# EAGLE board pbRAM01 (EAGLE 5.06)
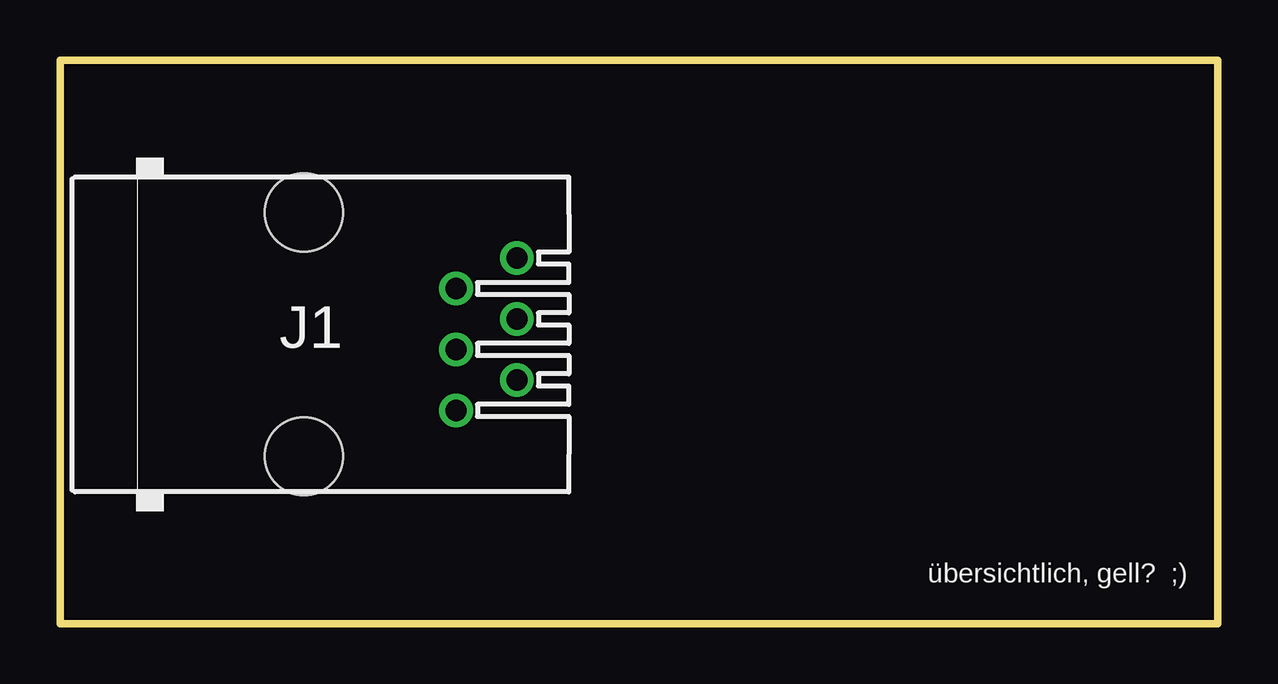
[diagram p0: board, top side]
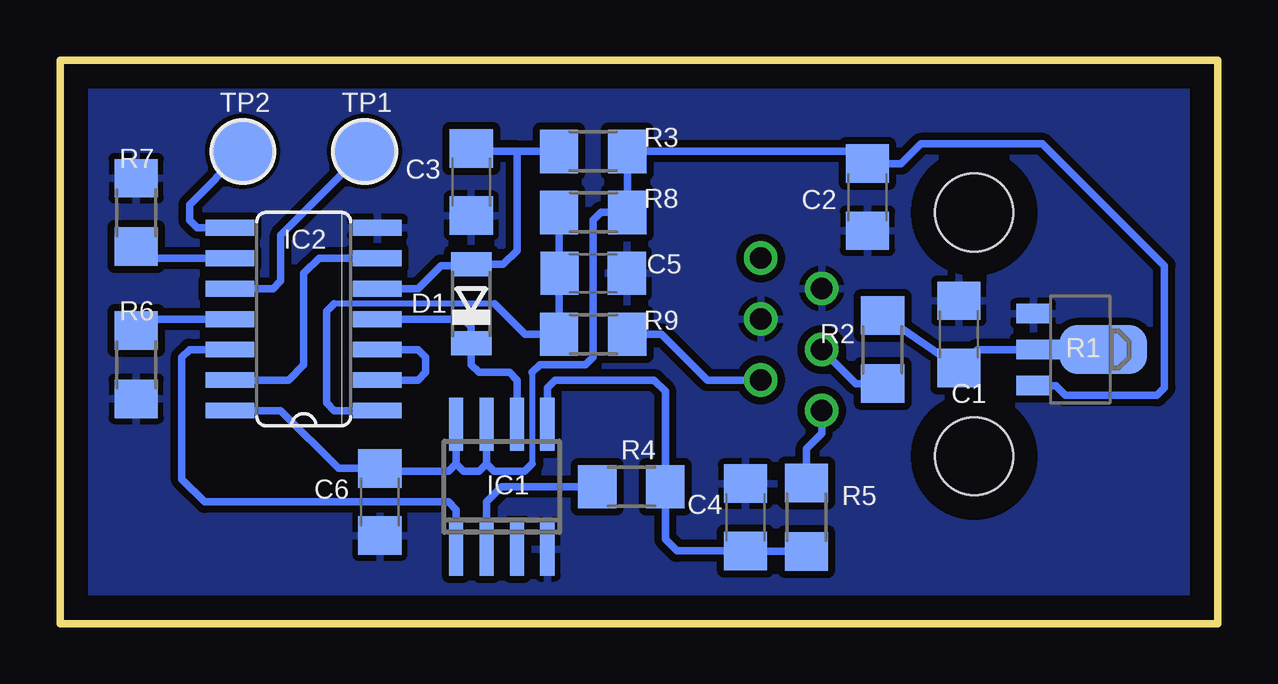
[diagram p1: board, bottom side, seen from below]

Size 48.26 x 23.5 mm. Coordinates in mm from the lower left corner, seen from the top.
Outline: 0,0 48.26,0 48.26,23.5 0,23.5 0,0
Copper layers (1*16): Top 0.035mm / dielectric 1.5mm / Bottom 0.035mm
Design rules "default": minimum track width 10mil, minimum drill 24mil, track to track 8mil, track to pad 8mil, pad to pad 8mil, via to via 8mil, smd to smd 8mil, copper to edge 40mil, drill to drill 8mil, minimum pad ring 10mil, minimum via ring 8mil, stop-mask expansion 4mil, vias tented up to drill 0mil, thermal gap 10mil

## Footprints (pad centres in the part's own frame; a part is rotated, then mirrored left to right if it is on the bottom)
C1206 = smd 1.6 x 1.8: 1 -1.4,0; 2 1.4,0
SOD80-R = smd 1 x 1.7: A 1.65,0; C -1.65,0
SO8 = smd 0.6 x 2.2: 1 -1.905,-2.6; 2 -0.635,-2.6; 3 0.635,-2.6; 4 1.905,-2.6; 5 1.905,2.6; 6 0.635,2.6; 7 -0.635,2.6; 8 -1.905,2.6
SO14 = smd 0.66 x 2.032: 1 -3.81,-3.073; 2 -2.54,-3.073; 3 -1.27,-3.073; 4 0,-3.073; 5 1.27,-3.073; 6 2.54,-3.073; 7 3.81,-3.073; 8 3.81,3.073; 9 2.54,3.073; 10 1.27,3.073; 11 0,3.073; 12 -1.27,3.073; 13 -2.54,3.073; 14 -3.81,3.073
520250-3 = drill 0.889 round: 1 -3.175,8.89; 2 -1.905,6.35; 3 -0.635,8.89; 4 0.635,6.35; 5 1.905,8.89; 6 3.175,6.35 | hole 3.251: -5.08,0; 5.08,0
SOT89 = smd 0.8 x 1.4: 1 -1.499,-1.981; 3 1.499,-1.981 | smd 0.8 x 1.9: 2 0,-1.727 | smd 2.032 x 3.65: 2@1 0,0.94
R1206 = smd 1.6 x 1.803: 1 -1.422,0; 2 1.422,0
B2,54 = smd 2.54 x 2.54: PP 0,0

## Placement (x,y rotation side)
C1  1u,6v3,cer  [C1206]  10.79,12.06 90 bottom
C2  1u,6v3,cer  [C1206]  14.61,17.78 270 bottom
C3  2n2  [C1206]  31.11,18.41 270 bottom
C4  47p  [C1206]  19.68,4.45 90 bottom
C5  47p  [C1206]  26.04,14.61 0 bottom
C6  100n  [C1206]  34.92,5.08 270 bottom
D1  LL103  [SOD80-R]  31.11,13.34 90 bottom
IC1  23K256  [SO8]  29.84,5.71 0 bottom
IC2  74HC14D  [SO14]  38.1,12.7 90 bottom
J1  [520250-3]  10.16,12.06 270 top
R1  S817A33  [SOT89]  5.71,11.43 270 bottom
R2  22E  [R1206]  13.97,11.43 90 bottom
R3  220k  [R1206]  26.04,19.68 0 bottom
R4  1k  [R1206]  24.45,5.71 180 bottom
R5  1k  [R1206]  17.14,4.45 270 bottom
R6  220k  [R1206]  45.09,10.79 270 bottom
R7  220k  [R1206]  45.09,17.14 90 bottom
R8  220k  [R1206]  26.04,17.14 180 bottom
R9  1k  [R1206]  26.04,12.06 180 bottom
TP1  [B2,54]  35.56,19.68 0 bottom
TP2  [B2,54]  40.64,19.68 0 bottom

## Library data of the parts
C1-C6 = rcl
D1 IC1 R1-R9 = Akki
IC2 = 74xx-eu
J1 = con-amp
TP1 TP2 = testpad

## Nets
+3V3: C2.1 C6.1 IC1.7 IC1.8 IC2.14 R1.3 R3.2 R8.1
GND: C1.2 C2.2 C3.2 C4.2 C5.2 C6.2 IC1.4 IC2.7 J1.2 J1.3 R1.1 R6.2 R7.2
N$1: D1.C IC1.6 IC2.4
N$2: J1.4 R2.1
N$3: C1.1 R1.2 R2.2
N$4: C3.1 D1.A IC2.5 R3.1
N$5: IC2.6 IC2.13
N$6: IC1.1 IC2.12
N$7: J1.5 R9.1
N$8: IC2.2 IC2.3
N$9: IC1.2 R4.2
N$10: J1.6 R5.1
N$11: C4.1 IC1.5 R4.1 R5.2
N$12: C5.1 IC2.1 R8.2 R9.2
N$13: IC2.11 R6.1
N$14: IC2.9 R7.1
N$15: IC2.10 TP1.PP
N$16: IC2.8 TP2.PP

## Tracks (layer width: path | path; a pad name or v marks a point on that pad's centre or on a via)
+3V3
  Bottom 0.254: 28.57,10.48 28.57,6.67
  Bottom 0.305: R1.3 6.76,9.93 6.35,9.53 2.54,9.53 2.22,9.84 2.22,14.92 7.3,20 12.38,20 13.21,19.18 C2.1 15.11,19.68 R3.2 R8.1 25.72,17.14 26.04,16.83 26.04,11.11 26.35,10.79 28.26,10.79 28.57,10.48 | 30.48,6.67 IC1.7 | 30.48,6.67 30.8,6.35 31.43,6.35 31.75,6.67 | 31.75,6.67 IC1.8 | 31.75,6.67 32.07,6.35 34.8,6.35 C6.1 36.64,6.48 39.05,8.89 IC2.14 | 28.57,6.67 28.89,6.35 30.16,6.35 30.48,6.67
GND
  pour Bottom (isolate 0.305): 0.64,22.23 47.62,22.86 47.62,0.64 0.64,0
N$1
  Bottom 0.305: IC2.4 31.43,12.7 31.11,12.38 D1.C 31.11,10.79 30.8,10.48 29.53,10.48 29.21,10.16 IC1.6
N$2
  Bottom 0.305: J1.4 15.09,10.01 R2.1
N$3
  Bottom 0.305: R2.2 C1.1 10.03,11.43 R1.2
N$4
  Bottom 0.305: 29.21,19.68 R3.1 | 29.21,19.68 30.98,19.68 C3.1 | IC2.5 33.34,13.97 32.38,14.92 31.18,14.92 D1.A 29.78,14.98 29.21,15.56 29.21,19.68
N$5
  Bottom 0.305: IC2.13 38.73,10.16 38.1,10.79 38.1,14.61 37.47,15.24 IC2.6
N$6
  Bottom 0.305: IC1.1 31.75,4.76 32.07,5.08 42.23,5.08 43.18,6.03 43.18,11.11 42.86,11.43 IC2.12
N$7
  Bottom 0.305: J1.5 21.27,10.16 23.18,12.06 R9.1
N$8
  Bottom 0.305: IC2.3 33.34,11.43 33.02,11.11 33.02,10.48 33.34,10.16 IC2.2
N$9
  Bottom 0.305: IC1.2 30.48,5.08 29.84,5.71 R4.2
N$10
  Bottom 0.305: J1.6 16.51,7.94 17.14,7.3 R5.1
N$11
  Bottom 0.305: R5.2 19.66,3.02 C4.1 22.54,3.04 23.03,3.53 R4.1 23.03,9.69 23.5,10.16 27.62,10.16 27.94,9.84 IC1.5
N$12
  Bottom 0.254: 30.15,13.34 36.83,13.34
  Bottom 0.305: R8.2 27.46,14.63 C5.1 27.46,14.58 R9.2 28.88,12.06 30.15,13.34 | IC2.1 36.83,8.89 37.15,9.21 37.15,13.02 36.83,13.34
N$13
  Bottom 0.305: IC2.11 44.6,12.7 R6.1
N$14
  Bottom 0.305: IC2.9 44.6,15.24 R7.1
N$15
  Bottom 0.305: IC2.10 39.37,13.97 39.05,14.29 39.05,16.19 TP1.PP
N$16
  Bottom 0.305: IC2.8 42.55,16.51 42.86,16.83 42.86,17.46 TP2.PP

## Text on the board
tPlace: übersichtlich, gell? ;)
